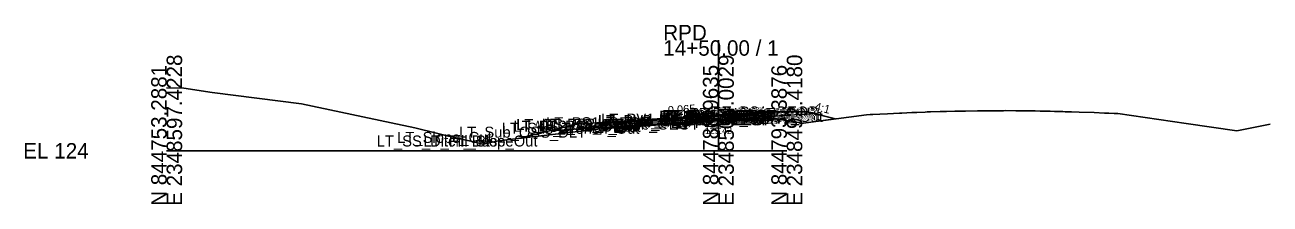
# Model space of a CAD drawing. Extents: x -26 to 2348536, y -510 to 844755.
# Drawn here: x -25.7 to 200, y -510.2 to -477.6 of the extents above; entities that cross this region are included whole.
import ezdxf

# ---------------------------------------------------------------- set-up
doc = ezdxf.new("R2010")
doc.units = 0
for name, color, linetype in [('Default', 7, 'Continuous'), ('Exist Cross Section Cell', 7, 'Continuous'), ('Exist XS Center Line Elevation Label', 7, 'Continuous'), ('Exist XS Ground Line', 7, 'Continuous'), ('Prop CMT Pvmt Course 1', 7, 'Continuous'), ('Prop CMT Pvmt Course 2', 7, 'Continuous'), ('Prop CMT Pvmt Course 3', 7, 'Continuous'), ('Prop CMT Pvmt Surface', 7, 'Continuous'), ('Prop CMT Pvmt Surface Shoulder', 7, 'Continuous'), ('Prop CMT Shld Paved Course 1', 7, 'Continuous'), ('Prop CMT Shld Paved Course 2', 7, 'Continuous'), ('Prop CMT Shld Paved Course 3', 7, 'Continuous'), ('Prop CMT Slope Grass', 7, 'Continuous'), ('Prop CMT Subgrade Earthwork', 7, 'Continuous'), ('Prop XS Earthwork Shape', 7, 'Continuous'), ('Prop XS Side Slope Text', 7, 'Continuous'), ('Scratch_Level_0', 7, 'Continuous')]:
    doc.layers.add(name, color=color, linetype=linetype)

msp = doc.modelspace()

# ---------------------------------------------------------------- linework, layer by layer
at = {"layer": 'Exist Cross Section Cell'}
for p, q in [((100, -500.49), (100, -480.42)), ((0, -500.49), (100, -500.49)), ((100, -500.49), (112.4, -500.49))]:
    msp.add_line(p, q, dxfattribs=at)
at = {"layer": 'Exist XS Ground Line'}
msp.add_lwpolyline([(0, -489.04), (3.11, -489.11), (8.26, -489.89), (24.42, -491.96), (40.72, -495.42), (45, -496.32), (49.15, -497.34), (50.83, -497.75), (54.53, -498.63), (54.87, -498.71), (57.32, -499.28), (59.85, -498.76), (60.26, -498.68), (62.68, -498.39), (78.69, -496.52), (79.4, -496.45), (79.78, -496.43), (81.45, -496.29), (82.22, -496.23), (82.57, -496.22), (83.82, -496.15), (85.15, -496.06), (85.96, -496), (87.79, -495.88), (88.63, -495.82), (90.48, -495.7), (90.88, -495.68), (92.5, -495.58), (93.14, -495.54), (93.86, -495.47), (95.01, -495.37), (95.77, -495.34), (97.83, -495.2), (98.48, -495.16), (98.88, -495.13), (100, -495.06), (101.16, -494.99), (102.18, -494.93), (104.11, -494.83), (104.82, -494.79), (106.05, -494.72), (106.53, -494.7), (108, -494.64), (109.26, -494.62), (110.18, -494.64), (114.56, -495.33), (114.95, -495.53), (126.82, -493.96), (127.52, -493.89), (127.97, -493.88), (129.24, -493.82), (130.68, -493.75), (132.81, -493.65), (133.28, -493.63), (135.09, -493.55), (135.97, -493.51), (137.51, -493.45), (137.86, -493.43), (138.43, -493.41), (140.18, -493.37), (141, -493.35), (141.32, -493.34), (142.87, -493.31), (144.01, -493.28), (144.81, -493.27), (146.97, -493.24), (149.44, -493.21), (150.2, -493.21), (151.65, -493.21), (152.06, -493.2), (153.94, -493.22), (154.67, -493.23), (155.13, -493.23), (157.4, -493.26), (158.35, -493.28), (160.11, -493.32), (160.92, -493.34), (162.46, -493.38), (162.85, -493.39), (164.03, -493.42), (165.41, -493.46), (168.09, -493.55), (169.97, -493.63), (170.79, -493.67), (171.75, -493.73), (172.4, -493.73), (184.79, -495.51), (193.98, -496.86), (200, -495.65)], dxfattribs=at)
at = {"layer": 'Prop CMT Pvmt Course 1'}
for p, q in [((100, -493.96), (88, -494.74)), ((88, -494.99), (100, -494.21)), ((100, -493.96), (104, -493.7)), ((104, -493.95), (100, -494.21)), ((100, -494.21), (100, -493.96)), ((100, -494.21), (100, -493.96)), ((100, -494.21), (100, -494.08)), ((100, -494.08), (100, -494.08)), ((100, -494.08), (100, -494.21)), ((100, -494.21), (100, -494.08)), ((100, -494.08), (100, -494.08)), ((100, -494.08), (100, -494.21)), ((100, -494.21), (100, -494.21)), ((100, -494.21), (100, -494.21)), ((104, -493.7), (104, -493.95)), ((88, -494.74), (88, -494.99))]:
    msp.add_line(p, q, dxfattribs=at)
at = {"layer": 'Prop CMT Pvmt Course 2'}
for p, q in [((100, -494.21), (88, -494.99)), ((100, -494.21), (104, -493.95)), ((100, -494.54), (100, -494.21)), ((100, -494.54), (100, -494.21)), ((104, -493.95), (104, -494.28)), ((88, -495.32), (100, -494.54)), ((88, -494.99), (88, -495.32)), ((104, -494.28), (100, -494.54))]:
    msp.add_line(p, q, dxfattribs=at)
at = {"layer": 'Prop CMT Pvmt Course 3'}
for p, q in [((100, -494.54), (88, -495.32)), ((88, -495.65), (100, -494.87)), ((88, -495.32), (88, -495.65)), ((100, -494.54), (104, -494.28)), ((100, -494.87), (100, -494.54)), ((100, -494.87), (100, -494.54)), ((104, -494.61), (100, -494.87)), ((104, -494.28), (104, -494.61))]:
    msp.add_line(p, q, dxfattribs=at)
at = {"layer": 'Prop CMT Pvmt Surface'}
for q in [(88, -494.74), (104, -493.7)]:
    msp.add_line((100, -493.96), q, dxfattribs=at)
at = {"layer": 'Prop CMT Pvmt Surface Shoulder'}
for p, q in [((104, -493.7), (108, -493.44)), ((88, -494.74), (78, -495.39))]:
    msp.add_line(p, q, dxfattribs=at)
at = {"layer": 'Prop CMT Shld Paved Course 1'}
for p, q in [((104, -493.7), (108, -493.44)), ((108.23, -493.67), (104, -493.95)), ((104, -493.95), (104, -493.7)), ((108, -493.44), (108.23, -493.67)), ((77.73, -495.65), (88, -494.99)), ((78, -495.39), (77.73, -495.65)), ((88, -494.74), (78, -495.39)), ((88, -494.99), (88, -494.74))]:
    msp.add_line(p, q, dxfattribs=at)
at = {"layer": 'Prop CMT Shld Paved Course 2'}
for p, q in [((104, -493.95), (108.23, -493.67)), ((104, -494.28), (104, -493.95)), ((108.55, -493.98), (104, -494.28)), ((108.23, -493.67), (108.55, -493.98)), ((77.38, -496.01), (88, -495.32)), ((77.73, -495.65), (77.38, -496.01)), ((88, -494.99), (77.73, -495.65)), ((88, -495.32), (88, -494.99))]:
    msp.add_line(p, q, dxfattribs=at)
at = {"layer": 'Prop CMT Shld Paved Course 3'}
for p, q in [((104, -494.28), (108.55, -493.98)), ((109.36, -494.26), (104, -494.61)), ((108.55, -493.98), (109.05, -493.95)), ((109.05, -493.95), (109.36, -494.26)), ((76.52, -496.4), (88, -495.65)), ((76.88, -496.04), (76.52, -496.4)), ((77.38, -496.01), (76.88, -496.04)), ((88, -495.32), (77.38, -496.01)), ((88, -495.65), (88, -495.32)), ((104, -494.61), (104, -494.28))]:
    msp.add_line(p, q, dxfattribs=at)
at = {"layer": 'Prop CMT Slope Grass'}
for p, q in [((108, -493.44), (116, -493.4)), ((116, -493.4), (121.22, -494.7)), ((74, -495.71), (63.78, -498.26)), ((78, -495.39), (74, -495.71))]:
    msp.add_line(p, q, dxfattribs=at)
at = {"layer": 'Prop CMT Subgrade Earthwork'}
for p, q in [((104, -494.61), (117.39, -493.74)), ((76.52, -496.4), (69.37, -496.86)), ((88, -495.65), (76.52, -496.4)), ((100, -494.87), (88, -495.65)), ((100, -494.87), (104, -494.61))]:
    msp.add_line(p, q, dxfattribs=at)
at = {"layer": 'Prop XS Earthwork Shape'}
msp.add_lwpolyline([(63.78, -498.26), (78.69, -496.52), (79.4, -496.45), (79.78, -496.43), (81.45, -496.29), (82.22, -496.23), (82.57, -496.22), (83.82, -496.15), (85.15, -496.06), (85.96, -496), (87.79, -495.88), (88.63, -495.82), (90.48, -495.7), (90.88, -495.68), (92.5, -495.58), (93.14, -495.54), (93.86, -495.47), (95.01, -495.37), (95.77, -495.34), (97.83, -495.2), (98.48, -495.16), (98.88, -495.13), (100, -495.06), (101.16, -494.99), (102.18, -494.93), (104.11, -494.83), (104.82, -494.79), (106.05, -494.72), (106.53, -494.7), (108, -494.64), (109.26, -494.62), (110.18, -494.64), (114.56, -495.33), (114.95, -495.53), (121.22, -494.7), (117.39, -493.74), (104, -494.61), (100, -494.87), (88, -495.65), (76.52, -496.4), (69.37, -496.86)], close=True, dxfattribs=at)

# ---------------------------------------------------------------- texts
at = {"layer": 'Default'}
msp.add_text('-', height=0.0001, dxfattribs=at).set_placement((0, -500.49))
at = {"layer": 'Exist Cross Section Cell'}
for s, p in [('RPD', (90, -480.42)), ('14+50.00 / 1', (90, -483.22)), ('EL 124', (-26, -501.89))]:
    msp.add_text(s, height=2.8, dxfattribs=at).set_placement(p)
for s, p in [('N 844753.2881', (0, -510.49)), ('E 2348597.4228', (2.8, -510.49)), ('N 844788.9635', (100, -510.49)), ('E 2348504.0029', (102.8, -510.49)), ('N 844793.3876', (112.4, -510.49)), ('E 2348492.4180', (115.2, -510.49))]:
    msp.add_text(s, height=2.8, rotation=90, dxfattribs=at).set_placement(p)
at = {"layer": 'Exist XS Center Line Elevation Label'}
msp.add_text('129.42', height=1.2, dxfattribs=at).set_placement((97.55, -497.43))
at = {"layer": 'Prop XS Side Slope Text'}
for s, rotation, p in [('4:1', 345.9638, (117.35, -493.1)), ('0.065', 3.719, (90.89, -493.88)), ('4:1', 14.0362, (66.9, -496.66))]:
    msp.add_text(s, height=1.5, rotation=rotation, dxfattribs=at).set_placement(p)
at = {"layer": 'Scratch_Level_0'}
for s, p in [('LT_PV2_OEOT', (78.17, -495.99)), ('LT_PV1_OEOT', (78.74, -495.74)), ('RT_Sub_OEEOP', (89.17, -495.87)), ('LT_Sub_OEEOP', (89.21, -495.87)), ('RT_PV2_OEEOP', (89.26, -495.21)), ('RT_PV3_OEEOP', (89.26, -495.54)), ('LT_PV2_OEEOP', (89.31, -495.21)), ('LT_PV3_OEEOP', (89.31, -495.54)), ('RT_PV1_OEEOP', (89.83, -495.08)), ('LT_PV1_OEEOP', (89.87, -495.08)), ('RT_PV2_IEEOP', (89.91, -495.21)), ('LT_PV2_IEEOP', (89.95, -495.21)), ('RT_PV1_IEEOP', (90.47, -495.08)), ('LT_PV1_IEEOP', (90.52, -495.08)), ('RT_Sub_Trench_Out', (93.52, -495.26)), ('PV2_PGL', (93.91, -495.21)), ('RT_Sub_OEOT', (94.03, -495.61)), ('RT_PV2_OEOT', (94.13, -494.95)), ('RT_PV3_OEOT', (94.13, -495.28)), ('PV1_PGL', (94.47, -494.96)), ('RT_PV1_OEOT', (94.69, -494.7)), ('RT_PS3_Shelf_Out', (94.98, -494.95)), ('RT_PS2_OEOP', (98.42, -494.67)), ('RT_PS3_OEOP', (98.74, -494.98)), ('RT_PS1_OEOP', (98.76, -494.44)), ('LT_Sub_OSS_DLT', (52.98, -498.11)), ('LT_Sub_Trench_Out', (60.72, -497.4)), ('LT_PS3_Shelf_Out', (62.86, -497.04)), ('LT_GS_OS_CTL', (63.37, -496.71)), ('LT_PS3_OEOP', (67.61, -497.01)), ('LT_PS2_OEOP', (67.97, -496.65)), ('LT_PS1_OEOP', (68.8, -496.39)), ('LT_Sub_OEOT', (78.08, -496.65)), ('LT_PV3_OEOT', (78.17, -496.32)), ('LT_SS_Ditch_Base_Out', (38.08, -499.71)), ('LT_Slope_Cut', (41.79, -499.06)), ('LT_Fill_Slope', (46.52, -499.71))]:
    msp.add_text(s, height=2, dxfattribs=at).set_placement(p)

doc.saveas('drawing.dxf')
